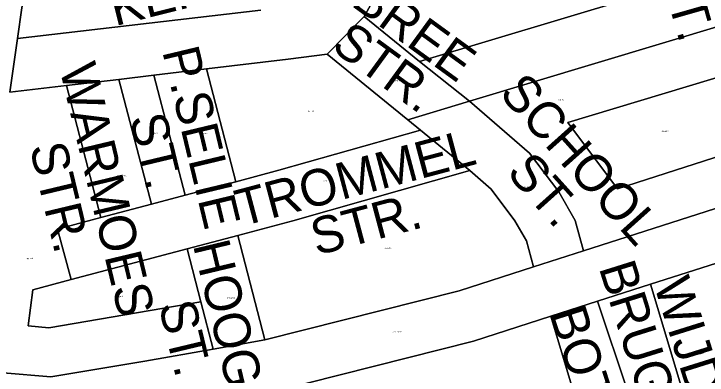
# Model space of a CAD drawing. Extents: x 14356 to 207184, y 3423 to 537581.
# Drawn here: x 132829.9 to 133028.5, y 516924.9 to 517028.5 of the extents above; entities that cross this region are included whole.
import ezdxf

# ---------------------------------------------------------------- set-up
doc = ezdxf.new("R2010")
doc.units = 0
for name, color, linetype in [('GEOCAD IKB VLAK TEKST CLASSIFICATIE', 7, 'Continuous'), ('PLATTEGROND ACHTERGROND BEBOUW', 7, 'Continuous'), ('PLATTEGROND BEBOUWING', 7, 'Continuous'), ('PLATTEGROND ERFTOEGANGSWEG', 7, 'Continuous'), ('PLATTEGROND GEB ONTSL WEG E', 7, 'Continuous'), ('PLATTEGROND HULPLIJN', 7, 'Continuous'), ('PLATTEGROND LIJN', 7, 'Continuous'), ('PLATTEGROND NAAM ERFTOEGANGSWEG', 7, 'Continuous'), ('PLATTEGROND NAAM GEB ONTSL WEG E', 7, 'Continuous'), ('PLATTEGROND VOET FIETSPAD', 7, 'Continuous')]:
    doc.layers.add(name, color=color, linetype=linetype)

msp = doc.modelspace()

# ---------------------------------------------------------------- linework, layer by layer
at = {"layer": 'PLATTEGROND ACHTERGROND BEBOUW'}
for p, q in [((132846.31, 516952.29), (132879.54, 516961.12)), ((132879.54, 516961.12), (132883.48, 516945.93))]:
    msp.add_line(p, q, dxfattribs=at)
for points in [[(133041.38, 516990.77), (133002.78, 516978.35), (132988.57, 516997.29), (133036.44, 517011.72)], [(132883.48, 516945.93), (132839.91, 516938.49), (132834, 516938.98), (132835.33, 516949.37), (132846.31, 516952.29)]]:
    msp.add_lwpolyline(points, dxfattribs=at)
at = {"layer": 'PLATTEGROND BEBOUWING'}
for p, q in [((133027.12, 517039.2), (132946.09, 517014.78)), ((132930.24, 517027.72), (132934.29, 517034.94)), ((132900.63, 517029.52), (132830.98, 517021.38)), ((132946.09, 517014.78), (132930.24, 517027.72)), ((132960.45, 517003.44), (133033.23, 517025.37)), ((132919.7, 517016.96), (132942.78, 516998.11)), ((132893.48, 516980.35), (132885.08, 517012.68)), ((132860.02, 517009.71), (132870.05, 517010.9)), ((132870.05, 517010.9), (132878.98, 516976.49)), ((132869.32, 516973.92), (132860.02, 517009.71)), ((132828.77, 517006.02), (132844.99, 517007.93)), ((132844.99, 517007.93), (132854.82, 516970.07)), ((132942.78, 516998.11), (132946.41, 516995.15)), ((133044.6, 516977.1), (132993.05, 516960.52)), ((132878.98, 516976.49), (132869.32, 516973.92)), ((132901.83, 516934.97), (132894.04, 516964.97)), ((133012.28, 516950.95), (133049.01, 516962.76)), ((133028.71, 516896.49), (133012.28, 516950.95)), ((132883.48, 516945.93), (132887.01, 516932.33)), ((132983.72, 516941.76), (133000.67, 516885.56))]:
    msp.add_line(p, q, dxfattribs=at)
for points in [[(132830.98, 517021.38), (132832.25, 517030.21), (132838.11, 517055.92)], [(132885.08, 517012.68), (132908.51, 517015.45), (132919.7, 517016.96)], [(133036.44, 517011.72), (132988.57, 516997.29), (133002.78, 516978.35), (133041.38, 516990.77)], [(132993.05, 516960.52), (132990.7, 516969.22), (132985.98, 516977.41), (132977.64, 516988.54), (132960.45, 517003.44)], [(132946.41, 516995.15), (132905.84, 516983.63), (132893.48, 516980.35)], [(132894.04, 516964.97), (132909.82, 516969.17), (132960.49, 516983.56)], [(132960.49, 516983.56), (132966.6, 516978.26), (132973.44, 516969.14), (132976.73, 516963.42), (132978.76, 516955.92)], [(132854.82, 516970.07), (132842.46, 516966.78), (132846.31, 516952.29)], [(132978.76, 516955.92), (132957.45, 516949.07), (132901.83, 516934.97)], [(132846.31, 516952.29), (132835.33, 516949.37), (132834, 516938.98), (132839.91, 516938.49), (132883.48, 516945.93)], [(132884.15, 516916.6), (132904.53, 516920.18), (132961.6, 516934.64), (132983.72, 516941.76)], [(132887.01, 516932.33), (132867.47, 516928.89), (132840.5, 516924.4), (132826.86, 516925.51), (132817.89, 516923.46)]]:
    msp.add_lwpolyline(points, dxfattribs=at)
at = {"layer": 'PLATTEGROND ERFTOEGANGSWEG'}
for p, q in [((132946.09, 517014.78), (133027.12, 517039.2)), ((132934.29, 517034.94), (132930.24, 517027.72)), ((132830.98, 517021.38), (132900.63, 517029.52)), ((132930.24, 517027.72), (132919.7, 517016.96)), ((132919.7, 517016.96), (132930.24, 517027.72)), ((132930.24, 517027.72), (132946.09, 517014.78)), ((133033.23, 517025.37), (132960.45, 517003.44)), ((132828.77, 517006.02), (132830.98, 517021.38)), ((132942.78, 516998.11), (132919.7, 517016.96)), ((132960.45, 517003.44), (132946.09, 517014.78)), ((132946.09, 517014.78), (132960.45, 517003.44)), ((132885.08, 517012.68), (132870.05, 517010.9)), ((132870.05, 517010.9), (132885.08, 517012.68)), ((132885.08, 517012.68), (132893.48, 516980.35)), ((132870.05, 517010.9), (132860.02, 517009.71)), ((132878.98, 516976.49), (132870.05, 517010.9)), ((132844.99, 517007.93), (132860.02, 517009.71)), ((132860.02, 517009.71), (132844.99, 517007.93)), ((132860.02, 517009.71), (132869.32, 516973.92)), ((132844.99, 517007.93), (132828.77, 517006.02)), ((132854.82, 516970.07), (132844.99, 517007.93)), ((132960.45, 517003.44), (132942.78, 516998.11)), ((132946.41, 516995.15), (132960.49, 516983.56)), ((132893.48, 516980.35), (132878.98, 516976.49)), ((132878.98, 516976.49), (132893.48, 516980.35)), ((132869.32, 516973.92), (132878.98, 516976.49)), ((132869.32, 516973.92), (132854.82, 516970.07)), ((132854.82, 516970.07), (132869.32, 516973.92)), ((132894.04, 516964.97), (132879.54, 516961.12)), ((132879.54, 516961.12), (132846.31, 516952.29))]:
    msp.add_line(p, q, dxfattribs=at)
for points in [[(132919.7, 517016.96), (132908.51, 517015.45), (132885.08, 517012.68)], [(132893.48, 516980.35), (132905.84, 516983.63), (132946.41, 516995.15)], [(132960.49, 516983.56), (132909.82, 516969.17), (132894.04, 516964.97)], [(132846.31, 516952.29), (132842.46, 516966.78), (132854.82, 516970.07)]]:
    msp.add_lwpolyline(points, dxfattribs=at)
at = {"layer": 'PLATTEGROND GEB ONTSL WEG E'}
for p, q in [((132830.98, 517021.38), (132828.77, 517006.02)), ((132993.05, 516960.52), (133044.6, 516977.1)), ((133049.01, 516962.76), (133012.28, 516950.95)), ((132978.76, 516955.92), (132993.05, 516960.52)), ((133012.28, 516950.95), (132997.14, 516946.08)), ((132997.14, 516946.08), (133012.28, 516950.95)), ((133012.28, 516950.95), (133028.71, 516896.49)), ((132997.14, 516946.08), (132983.72, 516941.76)), ((133015.43, 516891.4), (132997.14, 516946.08)), ((132887.01, 516932.33), (132901.83, 516934.97))]:
    msp.add_line(p, q, dxfattribs=at)
for points in [[(132838.11, 517055.92), (132832.25, 517030.21), (132830.98, 517021.38)], [(132901.83, 516934.97), (132957.45, 516949.07), (132978.76, 516955.92)], [(132983.72, 516941.76), (132961.6, 516934.64), (132904.53, 516920.18), (132884.15, 516916.6)], [(132817.89, 516923.46), (132826.86, 516925.51), (132840.5, 516924.4), (132867.47, 516928.89), (132887.01, 516932.33)]]:
    msp.add_lwpolyline(points, dxfattribs=at)
at = {"layer": 'PLATTEGROND HULPLIJN'}
for p, q in [((132919.7, 517016.96), (132930.24, 517027.72)), ((132830.98, 517021.38), (132828.77, 517006.02)), ((132946.09, 517014.78), (132960.45, 517003.44)), ((132870.05, 517010.9), (132885.08, 517012.68)), ((132844.99, 517007.93), (132860.02, 517009.71)), ((132960.45, 517003.44), (132942.78, 516998.11)), ((132946.41, 516995.15), (132960.49, 516983.56)), ((132878.98, 516976.49), (132893.48, 516980.35)), ((132869.32, 516973.92), (132854.82, 516970.07)), ((132879.54, 516961.12), (132894.04, 516964.97)), ((132978.76, 516955.92), (132993.05, 516960.52)), ((133012.28, 516950.95), (132997.14, 516946.08)), ((132887.01, 516932.33), (132901.83, 516934.97))]:
    msp.add_line(p, q, dxfattribs=at)
at = {"layer": 'PLATTEGROND LIJN'}
for p, q in [((133027.12, 517039.2), (132946.09, 517014.78)), ((132930.24, 517027.72), (132934.29, 517034.94)), ((132900.63, 517029.52), (132830.98, 517021.38)), ((132946.09, 517014.78), (132930.24, 517027.72)), ((133033.23, 517025.37), (132960.45, 517003.44)), ((132919.7, 517016.96), (132942.78, 516998.11)), ((132893.48, 516980.35), (132885.08, 517012.68)), ((132860.02, 517009.71), (132870.05, 517010.9)), ((132870.05, 517010.9), (132878.98, 516976.49)), ((132869.32, 516973.92), (132860.02, 517009.71)), ((132844.99, 517007.93), (132828.77, 517006.02)), ((132854.82, 516970.07), (132844.99, 517007.93)), ((132942.78, 516998.11), (132946.41, 516995.15)), ((132993.05, 516960.52), (133044.6, 516977.1)), ((132878.98, 516976.49), (132869.32, 516973.92)), ((132901.83, 516934.97), (132894.04, 516964.97)), ((132846.31, 516952.29), (132879.54, 516961.12)), ((132879.54, 516961.12), (132883.48, 516945.93)), ((133012.28, 516950.95), (133049.01, 516962.76)), ((133028.71, 516896.49), (133012.28, 516950.95)), ((132887.01, 516932.33), (132883.48, 516945.93)), ((132997.14, 516946.08), (132983.72, 516941.76)), ((133015.43, 516891.4), (132997.14, 516946.08)), ((133000.67, 516885.56), (132983.72, 516941.76))]:
    msp.add_line(p, q, dxfattribs=at)
for points in [[(132830.98, 517021.38), (132832.25, 517030.21), (132838.11, 517055.92)], [(132885.08, 517012.68), (132908.51, 517015.45), (132919.7, 517016.96)], [(133041.38, 516990.77), (133002.78, 516978.35), (132988.57, 516997.29), (133036.44, 517011.72)], [(132960.45, 517003.44), (132977.64, 516988.54), (132985.98, 516977.41), (132990.7, 516969.22), (132993.05, 516960.52)], [(132946.41, 516995.15), (132905.84, 516983.63), (132893.48, 516980.35)], [(132894.04, 516964.97), (132909.82, 516969.17), (132960.49, 516983.56)], [(132978.76, 516955.92), (132976.73, 516963.42), (132973.44, 516969.14), (132966.6, 516978.26), (132960.49, 516983.56)], [(132846.31, 516952.29), (132842.46, 516966.78), (132854.82, 516970.07)], [(132901.83, 516934.97), (132957.45, 516949.07), (132978.76, 516955.92)], [(132846.31, 516952.29), (132835.33, 516949.37), (132834, 516938.98), (132839.91, 516938.49), (132883.48, 516945.93)], [(132884.15, 516916.6), (132904.53, 516920.18), (132961.6, 516934.64), (132983.72, 516941.76)], [(132817.89, 516923.46), (132826.86, 516925.51), (132840.5, 516924.4), (132867.47, 516928.89), (132887.01, 516932.33)]]:
    msp.add_lwpolyline(points, dxfattribs=at)
at = {"layer": 'PLATTEGROND VOET FIETSPAD'}
for p, q in [((132942.78, 516998.11), (132960.45, 517003.44)), ((132946.41, 516995.15), (132942.78, 516998.11)), ((132960.49, 516983.56), (132946.41, 516995.15)), ((132879.54, 516961.12), (132894.04, 516964.97)), ((132894.04, 516964.97), (132901.83, 516934.97)), ((132883.48, 516945.93), (132879.54, 516961.12)), ((132993.05, 516960.52), (132978.76, 516955.92)), ((132887.01, 516932.33), (132883.48, 516945.93)), ((132983.72, 516941.76), (132997.14, 516946.08)), ((132997.14, 516946.08), (133015.43, 516891.4)), ((133000.67, 516885.56), (132983.72, 516941.76)), ((132901.83, 516934.97), (132887.01, 516932.33))]:
    msp.add_line(p, q, dxfattribs=at)
for points in [[(132960.45, 517003.44), (132977.64, 516988.54), (132985.98, 516977.41), (132990.7, 516969.22), (132993.05, 516960.52)], [(132978.76, 516955.92), (132976.73, 516963.42), (132973.44, 516969.14), (132966.6, 516978.26), (132960.49, 516983.56)]]:
    msp.add_lwpolyline(points, dxfattribs=at)

# ---------------------------------------------------------------- texts
at = {"layer": 'GEOCAD IKB VLAK TEKST CLASSIFICATIE'}
for s, p in [('CPG_ERFW', (132938.92, 517009.14)), ('cpg_bw1', (132985.86, 517003.66)), ('cpg_bw1', (132914.03, 517000.41)), ('cpg_grn2', (133015.41, 516994.73)), ('cpg_bw1', (132869.2, 516994.16)), ('CPG_ERFW', (132882.78, 516994.01)), ('CPG_ERFW', (132859.47, 516981.88)), ('CPG_ERFW', (132918.61, 516980.47)), ('CPG_PAD', (132975.45, 516978.68)), ('cpg_bw1', (132936.15, 516961.18)), ('cpg_bw1', (132833.54, 516958.19)), ('cpg_grn2', (132859.09, 516947.32)), ('CPG_PAD', (132890.96, 516946.84)), ('CPG_WEGE', (132938.37, 516937.14)), ('cpg_bw1', (133025.58, 516930.99))]:
    msp.add_text(s, height=0.35, dxfattribs=at).set_placement(p)
at = {"layer": 'PLATTEGROND NAAM ERFTOEGANGSWEG'}
for s, rotation, p in [('JEROENEN', 285.8825, (133020.51, 517070.29)), ('LANGE KERKSTR.', 18.2632, (132733.07, 517020.26)), ('KERK', 14.0871, (132858.9, 517024.94)), ('ST.', 285.8825, (133014.77, 517040.79)), ('BREE', 323.8786, (132926.19, 517031.08)), ('STR.', 323.8786, (132920.45, 517018.45)), ('P.SELIE', 283.4679, (132872.39, 517017.77)), ('WARMOES', 283.4679, (132842.94, 517012.92)), ('SCHOOL', 311.8685, (132968.62, 517005.48)), ('ST.', 283.4679, (132863, 516998.66)), ('TROMMEL', 14.8981, (132895.11, 516967.48)), ('STR.', 283.4679, (132834.38, 516990.35)), ('ST.', 311.8685, (132970.73, 516982.77)), ('STR.', 14.8981, (132916.62, 516959.14)), ('HOOGE', 283.4679, (132881.18, 516962.25)), ('ST.', 283.4679, (132871.34, 516944.99)), ('BOTTEL', 287.7201, (132983.23, 516942.74))]:
    msp.add_text(s, height=10.5, rotation=rotation, dxfattribs=at).set_placement(p)
at = {"layer": 'PLATTEGROND NAAM GEB ONTSL WEG E'}
for s, p in [('BRUGST.', (132997.41, 516955.72)), ('WIJDE', (133013.13, 516951))]:
    msp.add_text(s, height=10.5, rotation=287.4022, dxfattribs=at).set_placement(p)

doc.saveas('drawing.dxf')
